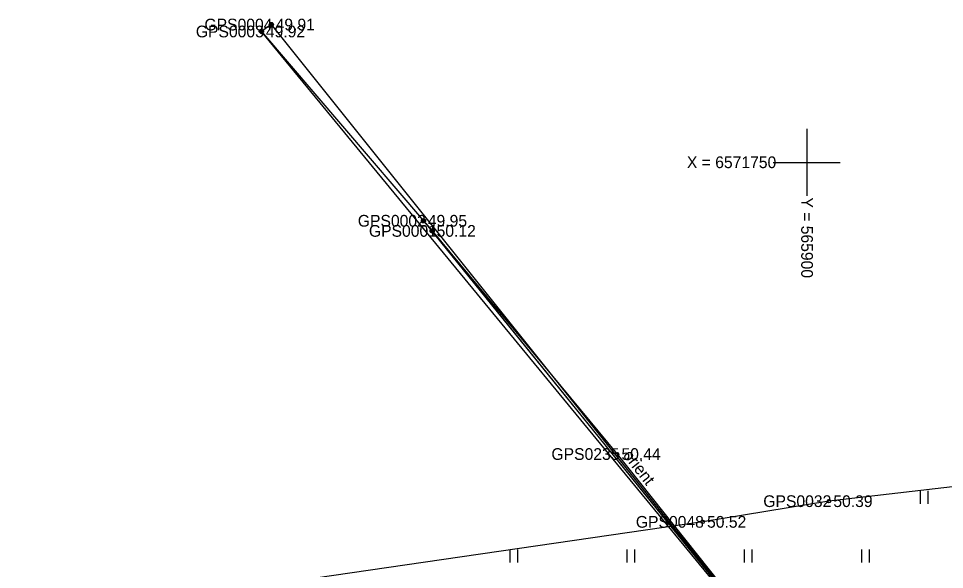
# Model space of a CAD drawing. Extents: x 563121 to 567545, y 6570841 to 6581299.
# Drawn here: x 565852.9 to 565908.2, y 6571725.7 to 6571758.6 of the extents above; entities that cross this region are included whole.
import ezdxf

# ---------------------------------------------------------------- set-up
doc = ezdxf.new("R2010")
doc.units = 0
for name, color, linetype in [('HALJASTUS', 7, 'Continuous'), ('KORGUS-EH2000', 7, 'Continuous'), ('MOOTKORG-EH2000', 7, 'Continuous'), ('MOOTMPUNKT', 7, 'Continuous'), ('MOOTNR', 7, 'Continuous'), ('MOOTPIIR', 7, 'Continuous'), ('MPKAABEL', 7, 'Continuous'), ('POST', 7, 'Continuous'), ('VORK', 7, 'Continuous')]:
    doc.layers.add(name, color=color, linetype=linetype)

msp = doc.modelspace()

# ---------------------------------------------------------------- linework, layer by layer
at = {"layer": 'HALJASTUS'}
for p, q in [((565906.772, 6571730.381), (565906.772, 6571729.619)), ((565907.228, 6571730.381), (565907.228, 6571729.619)), ((565882.272, 6571726.881), (565882.272, 6571726.119)), ((565882.728, 6571726.881), (565882.728, 6571726.119)), ((565889.272, 6571726.881), (565889.272, 6571726.119)), ((565889.728, 6571726.881), (565889.728, 6571726.119)), ((565896.272, 6571726.881), (565896.272, 6571726.119)), ((565896.728, 6571726.881), (565896.728, 6571726.119)), ((565903.272, 6571726.881), (565903.272, 6571726.119)), ((565903.728, 6571726.881), (565903.728, 6571726.119))]:
    msp.add_line(p, q, dxfattribs=at)
at = {"layer": 'KORGUS-EH2000'}
for centre in [(565901.33, 6571729.772), (565893.791, 6571728.537)]:
    msp.add_circle(centre, 0.1, dxfattribs=at)
at = {"layer": 'MOOTMPUNKT'}
for centre in [(565868.038, 6571758.236), (565867.453, 6571757.822), (565877.123, 6571746.517), (565877.646, 6571745.913), (565888.681, 6571732.586), (565901.33, 6571729.772), (565893.791, 6571728.537)]:
    msp.add_circle(centre, 0.1, dxfattribs=at)
at = {"layer": 'MOOTPIIR'}
msp.add_lwpolyline([(565847.666, 6571692.22), (565872.552, 6571695.122), (565896.74, 6571698.337), (565923.667, 6571701.7), (565921.225, 6571716.927), (565918.14, 6571731.716), (565901.33, 6571729.772), (565893.791, 6571728.537), (565867.263, 6571724.668), (565843.294, 6571721.486)], dxfattribs=at)
at = {"layer": 'MPKAABEL'}
msp.add_lwpolyline([(565868.038, 6571758.236), (565867.453, 6571757.822), (565877.123, 6571746.517), (565877.646, 6571745.913), (565888.681, 6571732.586), (565894.796, 6571724.904), (565901.066, 6571716.93)], dxfattribs=at)
at = {"layer": 'POST'}
for points in [[(565868.038, 6571758.236), (565901.066, 6571716.93), (565867.453, 6571757.822)], [(565877.123, 6571746.517), (565901.066, 6571716.93), (565877.646, 6571745.913)]]:
    msp.add_lwpolyline(points, dxfattribs=at)
for centre, radius in [((565868.038, 6571758.236), 0.125), ((565868.038, 6571758.236), 0.105), ((565868.038, 6571758.236), 0.0851), ((565868.038, 6571758.236), 0.0651), ((565868.038, 6571758.236), 0.0451), ((565868.038, 6571758.236), 0.0251), ((565868.038, 6571758.236), 0.00511), ((565867.453, 6571757.822), 0.125), ((565867.453, 6571757.822), 0.105), ((565867.453, 6571757.822), 0.0851), ((565867.453, 6571757.822), 0.0651), ((565867.453, 6571757.822), 0.0451), ((565867.453, 6571757.822), 0.0251), ((565867.453, 6571757.822), 0.00511), ((565877.123, 6571746.517), 0.125), ((565877.123, 6571746.517), 0.105), ((565877.123, 6571746.517), 0.0851), ((565877.123, 6571746.517), 0.0651), ((565877.123, 6571746.517), 0.0451), ((565877.123, 6571746.517), 0.0251), ((565877.123, 6571746.517), 0.00511), ((565877.646, 6571745.913), 0.125), ((565877.646, 6571745.913), 0.105), ((565877.646, 6571745.913), 0.0851), ((565877.646, 6571745.913), 0.0651), ((565877.646, 6571745.913), 0.0451), ((565877.646, 6571745.913), 0.0251), ((565877.646, 6571745.913), 0.00511)]:
    msp.add_circle(centre, radius, dxfattribs=at)
at = {"layer": 'VORK'}
for p, q in [((565900, 6571752), (565900, 6571748)), ((565898, 6571750), (565902, 6571750))]:
    msp.add_line(p, q, dxfattribs=at)

# ---------------------------------------------------------------- texts
at = {"layer": 'KORGUS-EH2000'}
for s, p in [(' 50.39', (565901.33, 6571729.422)), (' 50.52', (565893.791, 6571728.187))]:
    msp.add_text(s, height=0.7, dxfattribs=at).set_placement(p)
at = {"layer": 'MOOTKORG-EH2000'}
for s, p in [(' 49.92', (565867.453, 6571757.472)), (' 49.91', (565868.038, 6571757.886)), (' 49.95', (565877.123, 6571746.167)), (' 50.12', (565877.646, 6571745.563)), (' 50.44', (565888.681, 6571732.236)), (' 50.39', (565901.33, 6571729.422)), (' 50.52', (565893.791, 6571728.187))]:
    msp.add_text(s, height=0.7, dxfattribs=at).set_placement(p)
at = {"layer": 'MOOTNR'}
for s, p in [('GPS0003 ', (565863.534, 6571757.472)), ('GPS0004 ', (565864.048, 6571757.886)), ('GPS0002 ', (565873.203, 6571746.167)), ('GPS0001 ', (565873.866, 6571745.563)), ('GPS0235 ', (565884.762, 6571732.236)), ('GPS0032 ', (565897.41, 6571729.422)), ('GPS0048 ', (565889.801, 6571728.187))]:
    msp.add_text(s, height=0.7, dxfattribs=at).set_placement(p)
at = {"layer": 'MPKAABEL'}
msp.add_text('orient', height=0.7, rotation=308.1614, dxfattribs=at).set_placement((565888.998, 6571732.499))
at = {"layer": 'VORK'}
msp.add_text('X = 6571750', height=0.7, dxfattribs=at).set_placement((565892.848, 6571749.662))
msp.add_text('Y = 565900 ', height=0.7, rotation=270, dxfattribs=at).set_placement((565899.673, 6571747.912))

doc.saveas('drawing.dxf')
